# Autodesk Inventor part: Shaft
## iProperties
Created: 2011-05
Part Number: Shaft
Material: Steel
Document SubType Name: Modeling
Designer: 904Chiaki
Density: 7.85 g/cm^3
Mass: 12704.9 g
Surface Area: 1051.05 cm^2
Volume: 1618.46 cm^3
CustomPartVersion: 1
Author: 904Chiaki
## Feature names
1. Revolution1
2. Chamfer13
3. Chamfer5
4. Hole1
5. Chamfer14
6. Chamfer6
